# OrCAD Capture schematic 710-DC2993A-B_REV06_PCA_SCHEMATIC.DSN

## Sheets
1 PAGE1: size Custom
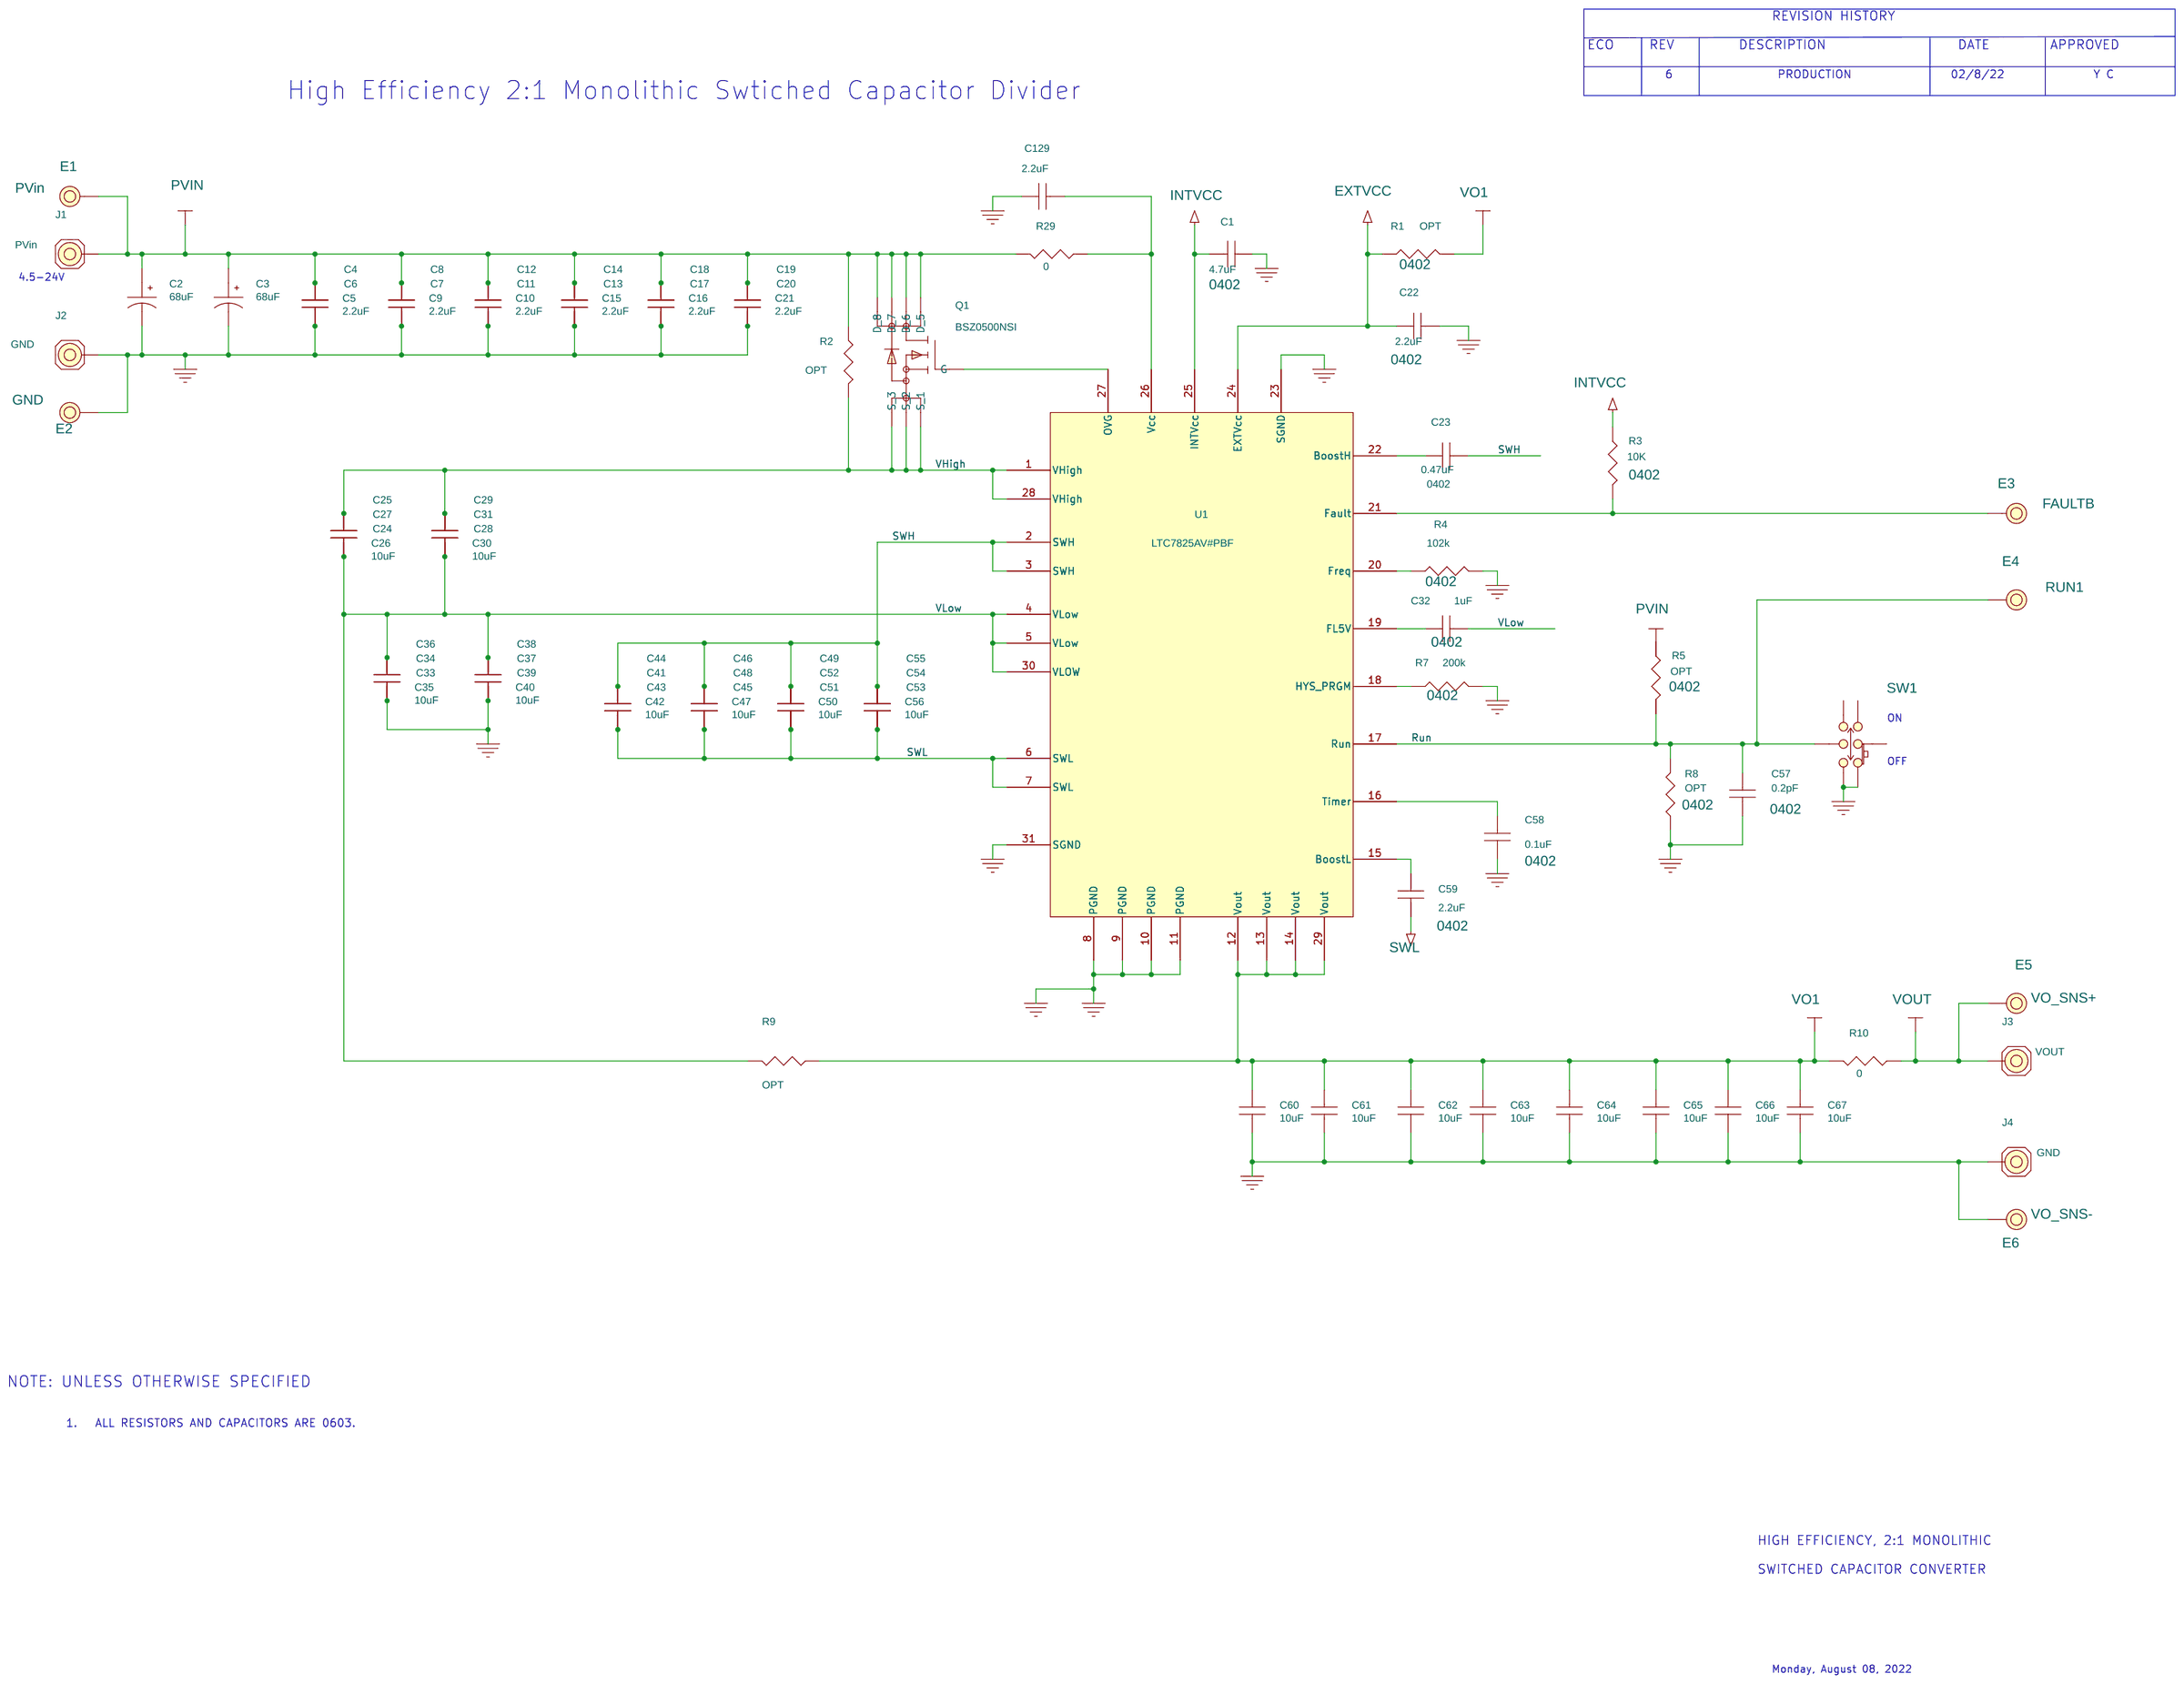
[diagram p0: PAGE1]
2 PAGE2: size Custom
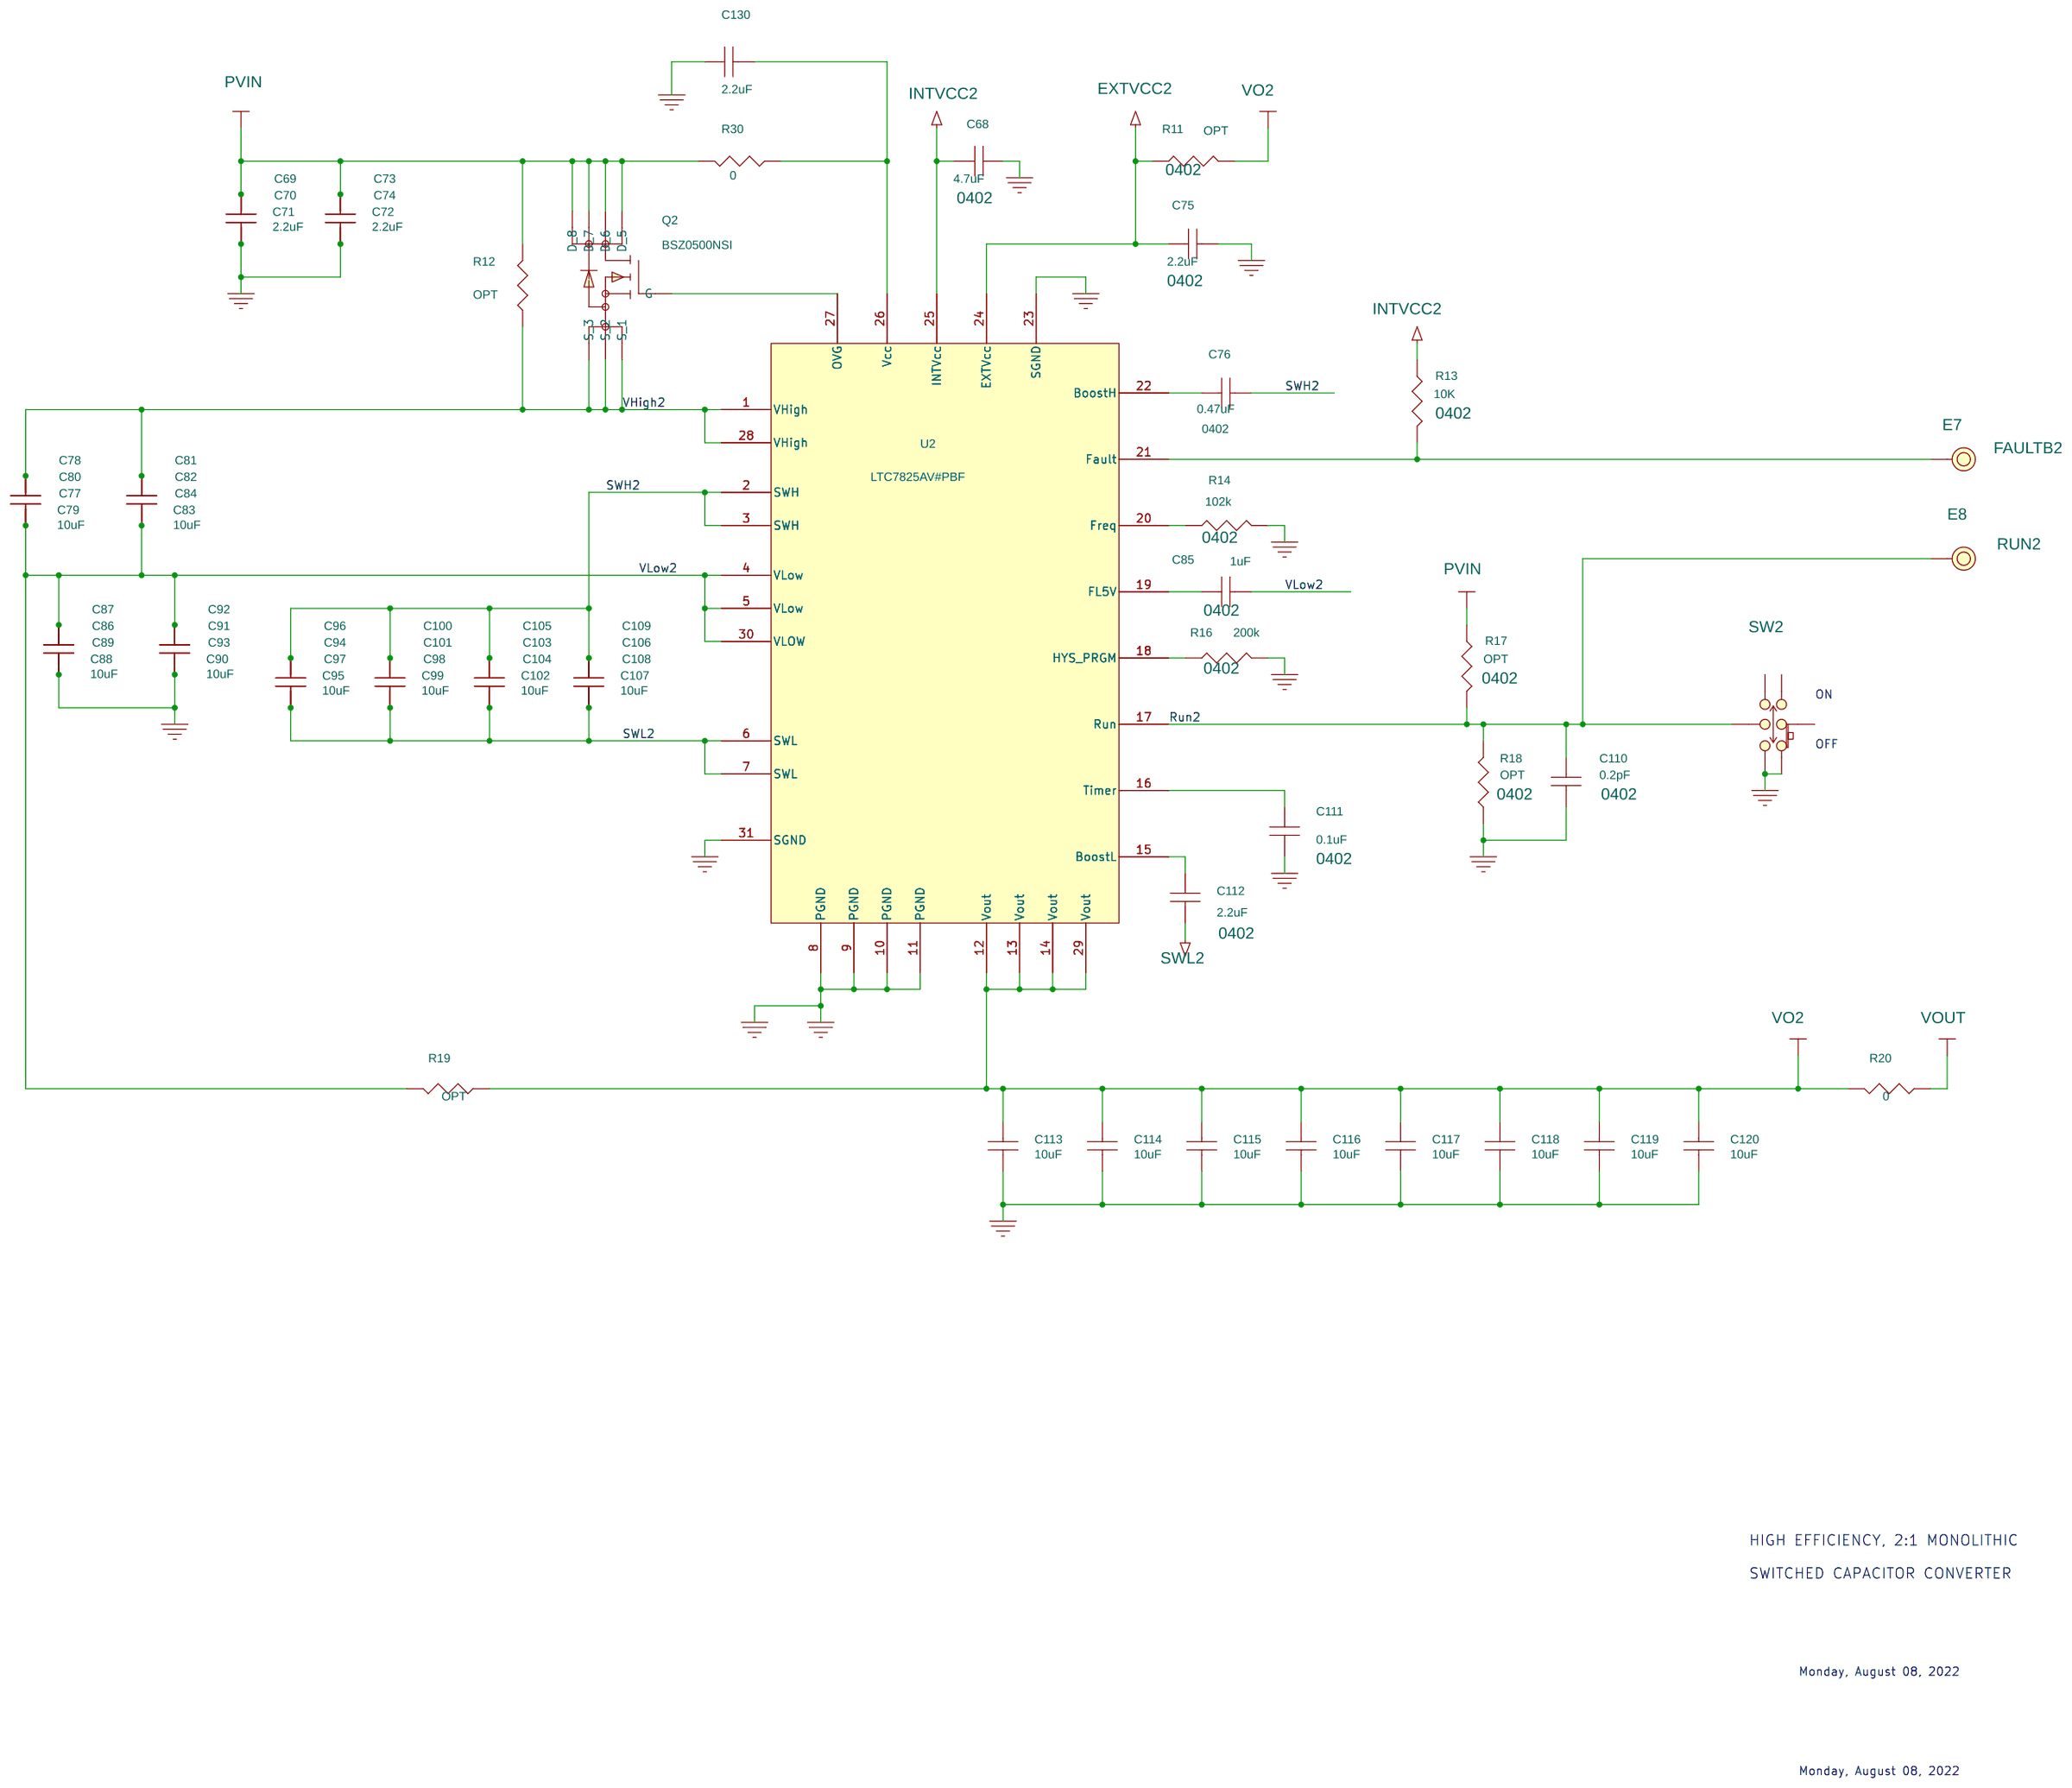
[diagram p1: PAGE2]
3 PAGE3: size Custom
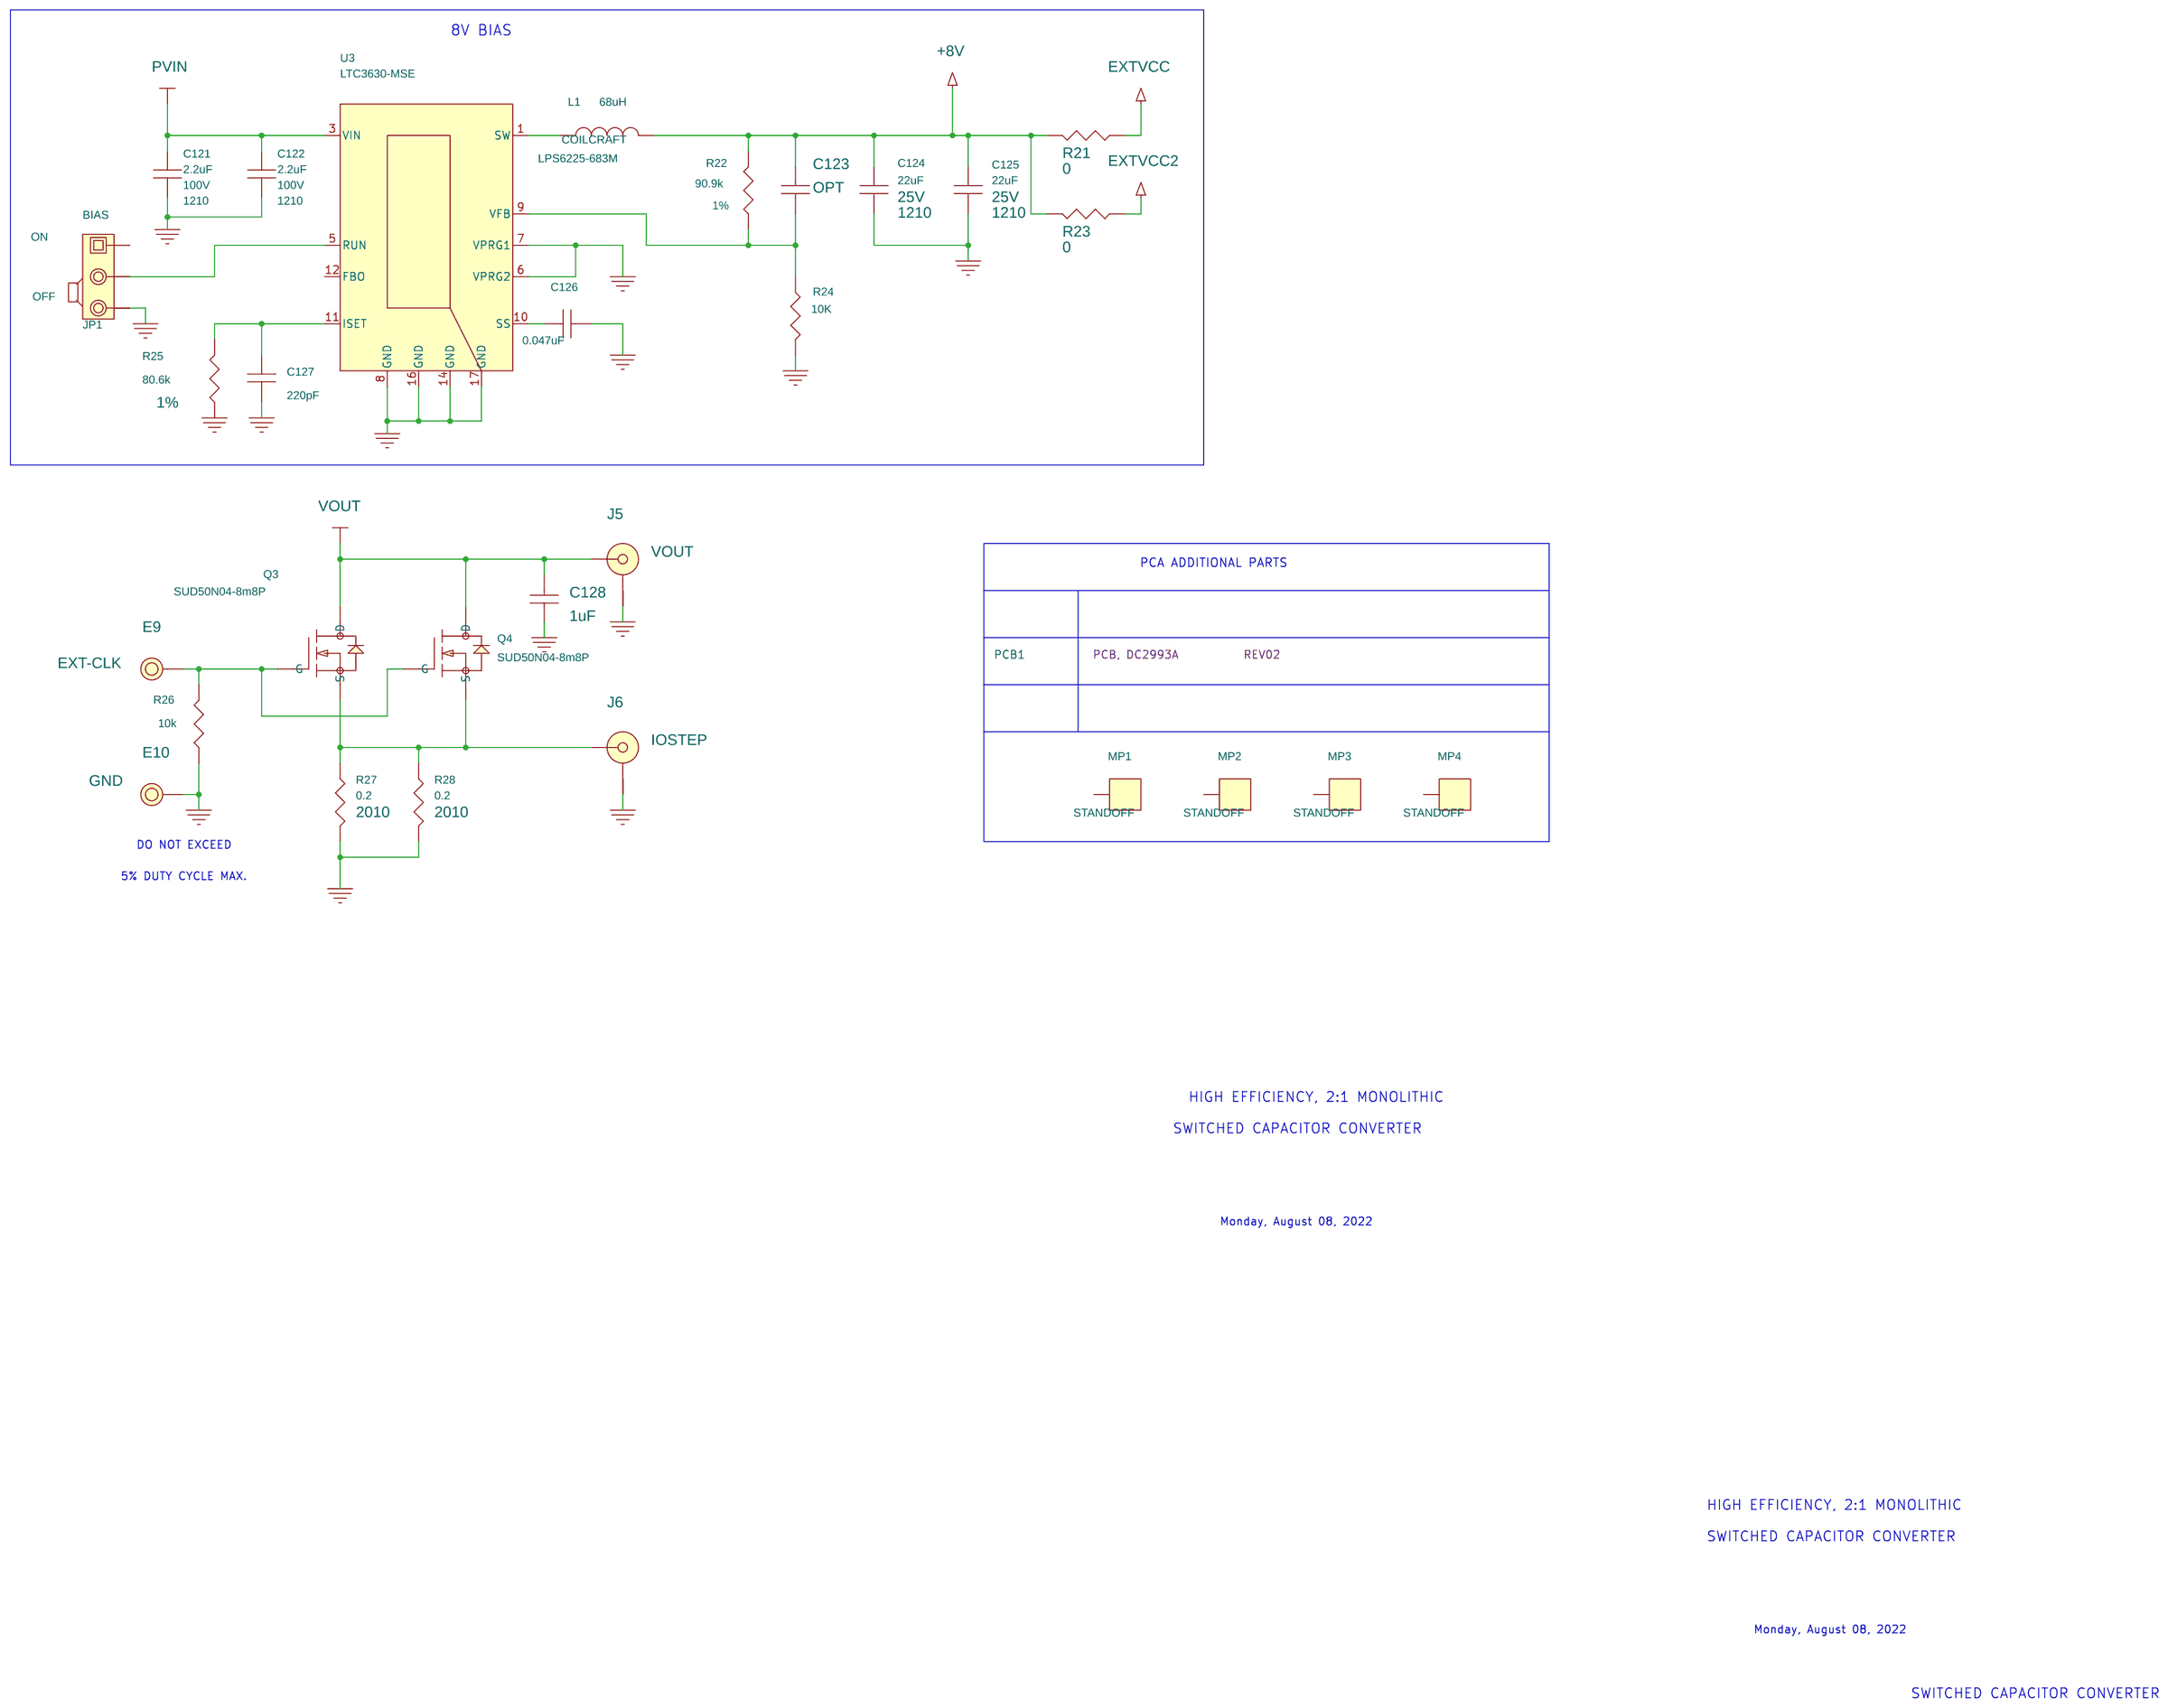
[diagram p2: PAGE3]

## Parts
sheet PAGE1
C1  4.7uF  [CC0402N]
C2  68uF  [NICHICON_GYA_8x10]
C3  68uF  [NICHICON_GYA_8x10]
C4  2.2uF  [CC0603N]
C5  2.2uF  [CC0603N]
C6  2.2uF  [CC0603N]
C7  2.2uF  [CC0603N]
C8  2.2uF  [CC0603N]
C9  2.2uF  [CC0603N]
C10  2.2uF  [CC0603N]
C11  2.2uF  [CC0603N]
C12  2.2uF  [CC0603N]
C13  2.2uF  [CC0603N]
C14  2.2uF  [CC0603N]
C15  2.2uF  [CC0603N]
C16  2.2uF  [CC0603N]
C17  2.2uF  [CC0603N]
C18  2.2uF  [CC0603N]
C19  2.2uF  [CC0603N]
C20  2.2uF  [CC0603N]
C21  2.2uF  [CC0603N]
C22  2.2uF  [CC0402N]
C23  0.47uF  [CC0402N]
C24  10uF  [CC0603N]
C25  10uF  [CC0603N]
C26  10uF  [CC0603N]
C27  10uF  [CC0603N]
C28  10uF  [CC0603N]
C29  10uF  [CC0603N]
C30  10uF  [CC0603N]
C31  10uF  [CC0603N]
C32  1uF  [CC0402N]
C33  10uF  [CC0603N]
C34  10uF  [CC0603N]
C35  10uF  [CC0603N]
C36  10uF  [CC0603N]
C37  10uF  [CC0603N]
C38  10uF  [CC0603N]
C39  10uF  [CC0603N]
C40  10uF  [CC0603N]
C41  10uF  [CC0603N]
C42  10uF  [CC0603N]
C43  10uF  [CC0603N]
C44  10uF  [CC0603N]
C45  10uF  [CC0603N]
C46  10uF  [CC0603N]
C47  10uF  [CC0603N]
C48  10uF  [CC0603N]
C49  10uF  [CC0603N]
C50  10uF  [CC0603N]
C51  10uF  [CC0603N]
C52  10uF  [CC0603N]
C53  10uF  [CC0603N]
C54  10uF  [CC0603N]
C55  10uF  [CC0603N]
C56  10uF  [CC0603N]
C57  0.2pF  [CC0402N]
C58  0.1uF  [CC0402N]
C59  2.2uF  [CC0402N]
C60  10uF  [CC0603N]
C61  10uF  [CC0603N]
C62  10uF  [CC0603N]
C63  10uF  [CC0603N]
C64  10uF  [CC0603N]
C65  10uF  [CC0603N]
C66  10uF  [CC0603N]
C67  10uF  [CC0603N]
C129  2.2uF  [CC0603N]
E1  TEST POINT  [MILLMAX2501]
E2  TEST POINT  [MILLMAX2501]
E3  TEST POINT  [MILLMAX2501]
E4  TEST POINT  [MILLMAX2501]
E5  TEST POINT  [MILLMAX2501]
E6  TEST POINT  [MILLMAX2501]
J1  STUD,#10-32  [PENN-KFH-032]
J2  STUD,#10-32  [PENN-KFH-032]
J3  STUD,#10-32  [PENN-KFH-032]
J4  STUD,#10-32  [PENN-KFH-032]
Q1  BSZ0500NSI  [INFINEON-PG-TSDSON-8-FL]
R1  OPT  [CR0402N]
R2  OPT  [CR0603N]
R3  10K  [CR0402N]
R4  102k  [CR0402N]
R5  OPT  [CR0402N]
R7  200k  [CR0402N]
R8  OPT  [CR0402N]
R9  OPT  [CR0603N]
R10  0  [CR0603N]
R29  0  [CR0603N]
SW1  DPDT  [C&K-JS202011CQN]
U1  LTC7825AV#PBF  [LTC-LQFN-28-7007]
sheet PAGE2
C68  4.7uF  [CC0402N]
C69  2.2uF  [CC0603N]
C70  2.2uF  [CC0603N]
C71  2.2uF  [CC0603N]
C72  2.2uF  [CC0603N]
C73  2.2uF  [CC0603N]
C74  2.2uF  [CC0603N]
C75  2.2uF  [CC0402N]
C76  0.47uF  [CC0402N]
C77  10uF  [CC0603N]
C78  10uF  [CC0603N]
C79  10uF  [CC0603N]
C80  10uF  [CC0603N]
C81  10uF  [CC0603N]
C82  10uF  [CC0603N]
C83  10uF  [CC0603N]
C84  10uF  [CC0603N]
C85  1uF  [CC0402N]
C86  10uF  [CC0603N]
C87  10uF  [CC0603N]
C88  10uF  [CC0603N]
C89  10uF  [CC0603N]
C90  10uF  [CC0603N]
C91  10uF  [CC0603N]
C92  10uF  [CC0603N]
C93  10uF  [CC0603N]
C94  10uF  [CC0603N]
C95  10uF  [CC0603N]
C96  10uF  [CC0603N]
C97  10uF  [CC0603N]
C98  10uF  [CC0603N]
C99  10uF  [CC0603N]
C100  10uF  [CC0603N]
C101  10uF  [CC0603N]
C102  10uF  [CC0603N]
C103  10uF  [CC0603N]
C104  10uF  [CC0603N]
C105  10uF  [CC0603N]
C106  10uF  [CC0603N]
C107  10uF  [CC0603N]
C108  10uF  [CC0603N]
C109  10uF  [CC0603N]
C110  0.2pF  [CC0402N]
C111  0.1uF  [CC0402N]
C112  2.2uF  [CC0402N]
C113  10uF  [CC0603N]
C114  10uF  [CC0603N]
C115  10uF  [CC0603N]
C116  10uF  [CC0603N]
C117  10uF  [CC0603N]
C118  10uF  [CC0603N]
C119  10uF  [CC0603N]
C120  10uF  [CC0603N]
C130  2.2uF  [CC0603N]
E7  TEST POINT  [MILLMAX2501]
E8  TEST POINT  [MILLMAX2501]
Q2  BSZ0500NSI  [INFINEON-PG-TSDSON-8-FL]
R11  OPT  [CR0402N]
R12  OPT  [CR0603N]
R13  10K  [CR0402N]
R14  102k  [CR0402N]
R16  200k  [CR0402N]
R17  OPT  [CR0402N]
R18  OPT  [CR0402N]
R19  OPT  [CR0603N]
R20  0  [CR0603N]
R30  0  [CR0603N]
SW2  DPDT  [C&K-JS202011CQN]
U2  LTC7825AV#PBF  [LTC-LQFN-28-7007]
sheet PAGE3
C121  2.2uF  [CC1210N]
C122  2.2uF  [CC1210N]
C123  OPT  [CC0603N]
C124  22uF  [CC1210N]
C125  22uF  [CC1210N]
C126  0.047uF  [CC0603N]
C127  220pF  [CC0603N]
C128  1uF  [CC0603N]
E9  TEST POINT  [MILLMAX2501]
E10  TEST POINT  [MILLMAX2501]
J5  RF,BNC  [CONNEX-112404]
J6  RF,BNC  [CONNEX-112404]
JP1  HDR  [HD1X3-079]
L1  68uH  [COILCRAFT-LPS6225]
LB1  LABEL  [895-0154_REV01]
LB4  LABEL  [895-0154_REV01]
LB5  LABEL  [EVAL-LTC4296-AZ]
MP1  STANDOFF  [KEYSTONE_8829-8834]
MP2  STANDOFF  [KEYSTONE_8829-8834]
MP3  STANDOFF  [KEYSTONE_8829-8834]
MP4  STANDOFF  [KEYSTONE_8829-8834]
PCB1  PCB, DC2993A
Q3  SUD50N04-8m8P  [TO-252-3N]
Q4  SUD50N04-8m8P  [TO-252-3N]
R21  0  [CR0603N]
R22  90.9k  [CR0603N]
R23  0  [CR0603N]
R24  10K  [CR0603N]
R25  80.6k  [CR0603N]
R26  10k  [CR0603N]
R27  0.2  [CR2010N]
R28  0.2  [CR2010N]
STNCL1  TOOL, STENCIL, 700-DC2993A
U3  LTC3630-MSE  [LTC-MSE-16-1871]
XJP1  SHUNT

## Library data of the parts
C1 C68 = CAP: CAP.,4.7uF,X5R,10V,10%,0402,NO SUBS. ALLOWED; CLASS: DISCRETE; Dielectric Type: X5R; FPLIST: CC0402N,CC0402L,CC0402M; Inventory Qty: 14000; Manufacturer: TDK; Manufacturer PN: C1005X5R1A475K050BC; PART_NUMBER: 150-2599; Package Size: 0402; Rated Voltage: 10V; Tolerance: 10%
C2 C3 = CAP_P_ALT: CAP.,68uF,ALUM POLY,50V,20%,SMD,8.3x8.3mm; CLASS: DISCRETE; Dielectric Type: ALUM POLY; Inventory Qty: 0; Manufacturer: Nichicon; Manufacturer PN: GYA1H680MCQ1GS; PART_NUMBER: 150-1214; Package Size: SMD,8.3x8.3mm; Package Type: Surface Mount; Rated Voltage: 50V; Tolerance: 20%
C4-C21 C69-C74 C129 C130 = CAP: CAP.,2.2uF,X5R,50V,10%,0603; CLASS: DISCRETE; Dielectric Type: X5R; FPLIST: CC0603N,CC0603L,CC0603M; Inventory Qty: 20200; Manufacturer: TAIYO YUDEN; Manufacturer PN: UMK107BBJ225KA-T; PART_NUMBER: 150-0229; Package Size: 0603; Package Type: Surface Mount, MLCC; Rated Voltage: 50V; Temperature Coefficient: X5R; Tolerance: 10%
C22 C59 C75 C112 = CAP: CAP.,2.2uF,X5R,25V,10%,0402; CLASS: DISCRETE; Dielectric Type: X5R; FPLIST: CC0402N,CC0402L,CC0402M; Inventory Qty: 19426; Manufacturer: MURATA; Manufacturer PN: GRM155R61E225KE11D; PART_NUMBER: 150-0271; Package Size: 0402; Rated Voltage: 25V; Tolerance: 10%
C23 C76 = CAP: CAP.,0.47uF,X5R,50V,10%,0402; CLASS: DISCRETE; Dielectric Type: X5R; FPLIST: CC0402N,CC0402L,CC0402M; Inventory Qty: 0; Manufacturer: MURATA; Manufacturer PN: GRM155R61H474KE11D; PART_NUMBER: 150-2644; Package Size: 0402; Rated Voltage: 50V; Tolerance: 10%
C24-C31 C33-C56 C60-C67 C77-C84 C86-C109 C113-C120 = CAP: CAP.,10uF,X5R,25V,20%,0603,NO SUBS. ALLOWED; CLASS: DISCRETE; Dielectric Type: X5R; FPLIST: CC0603N,CC0603L,CC0603M; Inventory Qty: 16160; Manufacturer: MURATA; Manufacturer PN: GRM188R61E106MA73D; PART_NUMBER: 150-2347; Package Size: 0603; Rated Voltage: 25V; Tolerance: 20%
C32 C85 = CAP: CAP.,1uF,X5R,25V,10%,0402; CLASS: DISCRETE; Dielectric Type: X5R; FPLIST: CC0402N,CC0402L,CC0402M; Inventory Qty: 20000; Manufacturer: MURATA; Manufacturer PN: GRM155R61E105KA12D; PART_NUMBER: 150-2562; Package Size: 0402; Rated Voltage: 25V; Tolerance: 10%
C57 C110 = CAP: CAP.,0.2pF,C0G,50V,+/-0.1pF,0402; CLASS: DISCRETE; Dielectric Type: C0G; FPLIST: CC0402N,CC0402L,CC0402M; Inventory Qty: 0; Manufacturer: MURATA; Manufacturer PN: GJM1555C1HR20BB01D; PART_NUMBER: 150-0532; Package Size: 0402; Rated Voltage: 50V; Tolerance: +/-0.1pF
C58 C111 = CAP: CAP.,0.1uF,X7R,25V,10%,0402,NO SUBS ALLOWED; CLASS: DISCRETE; Dielectric Type: X7R; FPLIST: CC0402N,CC0402L,CC0402M; Inventory Qty: 275; Manufacturer: MURATA; Manufacturer PN: GRM155R71E104KE14; PART_NUMBER: 150-0441; Package Size: 0402; Rated Voltage: 25V; Temperature Coefficient: X7R; Tolerance: 10%
E1 = TESTPOINT_.219_MILL-MAX_2501: TEST POINT,TURRET,0.094" MTG. HOLE,PCB 0.062" THK; 1st Part Field: PVin; CLASS: IO; Inventory Qty: 494204; Manufacturer: MILL-MAX; Manufacturer PN: 2501-2-00-80-00-00-07-0; PART_NUMBER: 260-0003; Part Number: MILL-MAX 2501-2-00-80-00-00-07-0
E2 E10 = TESTPOINT_.219_MILL-MAX_2501: TEST POINT,TURRET,0.094" MTG. HOLE,PCB 0.062" THK; 1st Part Field: GND; CLASS: IO; Inventory Qty: 494204; Manufacturer: MILL-MAX; Manufacturer PN: 2501-2-00-80-00-00-07-0; PART_NUMBER: 260-0003; Part Number: MILL-MAX 2501-2-00-80-00-00-07-0
E3 = TESTPOINT_.219_MILL-MAX_2501: TEST POINT,TURRET,0.094" MTG. HOLE,PCB 0.062" THK; 1st Part Field: FAULTB; CLASS: IO; Inventory Qty: 494204; Manufacturer: MILL-MAX; Manufacturer PN: 2501-2-00-80-00-00-07-0; PART_NUMBER: 260-0003; Part Number: MILL-MAX 2501-2-00-80-00-00-07-0
E4 = TESTPOINT_.219_MILL-MAX_2501: TEST POINT,TURRET,0.094" MTG. HOLE,PCB 0.062" THK; 1st Part Field: RUN1; CLASS: IO; Inventory Qty: 494204; Manufacturer: MILL-MAX; Manufacturer PN: 2501-2-00-80-00-00-07-0; PART_NUMBER: 260-0003; Part Number: MILL-MAX 2501-2-00-80-00-00-07-0
E5 = TESTPOINT_.219_MILL-MAX_2501: TEST POINT,TURRET,0.094" MTG. HOLE,PCB 0.062" THK; 1st Part Field: VO_SNS+; CLASS: IO; Inventory Qty: 494204; Manufacturer: MILL-MAX; Manufacturer PN: 2501-2-00-80-00-00-07-0; PART_NUMBER: 260-0003; Part Number: MILL-MAX 2501-2-00-80-00-00-07-0
E6 = TESTPOINT_.219_MILL-MAX_2501: TEST POINT,TURRET,0.094" MTG. HOLE,PCB 0.062" THK; 1st Part Field: VO_SNS-; CLASS: IO; Inventory Qty: 494204; Manufacturer: MILL-MAX; Manufacturer PN: 2501-2-00-80-00-00-07-0; PART_NUMBER: 260-0003; Part Number: MILL-MAX 2501-2-00-80-00-00-07-0
J1 = PEM-KFH: EVAL BOARD STUD HARDWARE SET, #10-32; 9th Part Field: PVin; CLASS: DISCRETE; Comments: CONSISTS OF QTY(1) STUD, 769-0012; QTY(1) RING LUG, 769-0013;QTY(2) HEX NUT,BRASS,761-0013; QTY(1) WASHER,#10 LOCK, 762-0021; Manufacturer: ANALOG DEVICES; Manufacturer PN: 720-0010; PART_NUMBER: 720-0010
J2 J4 = PEM-KFH: EVAL BOARD STUD HARDWARE SET, #10-32; 9th Part Field: GND; CLASS: DISCRETE; Comments: CONSISTS OF QTY(1) STUD, 769-0012; QTY(1) RING LUG, 769-0013;QTY(2) HEX NUT,BRASS,761-0013; QTY(1) WASHER,#10 LOCK, 762-0021; Manufacturer: ANALOG DEVICES; Manufacturer PN: 720-0010; PART_NUMBER: 720-0010
J3 = PEM-KFH: EVAL BOARD STUD HARDWARE SET, #10-32; 9th Part Field: VOUT; CLASS: DISCRETE; Comments: CONSISTS OF QTY(1) STUD, 769-0012; QTY(1) RING LUG, 769-0013;QTY(2) HEX NUT,BRASS,761-0013; QTY(1) WASHER,#10 LOCK, 762-0021; Manufacturer: ANALOG DEVICES; Manufacturer PN: 720-0010; PART_NUMBER: 720-0010
Q1 Q2 = 8P_N-CH_TYPE1A: XSTR.,MOSFET,N-CH,30V,40A,PG-TSDSON-8 FL; CLASS: DISCRETE; Inventory Qty: 0; Manufacturer: INFINEON; PART_NUMBER: 240-0470; Package Type: PG-TSDSON-8 FL; Rated Voltage: 30V
R1 R5 R8 R11 R17 R18 = RES: RES., OPTION, 0402; CLASS: DISCRETE; FPLIST: CR0402N,CR0402L,CR0402M; PART_NUMBER: 100-0357; Package Size: 0402
R2 R9 R12 R19 = RES: RES., OPTION, 0603; CLASS: DISCRETE; FPLIST: CR0603N,CR0603L,CR0603M; PART_NUMBER: 100-2374; Package Size: 0603
R3 R13 = RES: RES.,10K OHMS,0.1%,1/16W,0402; CLASS: DISCRETE; FPLIST: CR0402N,CR0402L,CR0402M; Inventory Qty: 19766; Manufacturer: YAGEO; Manufacturer PN: RT0402BRD0710KL; PART_NUMBER: 100-0575; Package Size: 0402; Rated Power: 1/16W; Temperature Coefficient: +/-25PPM; Tolerance: 0.1%
R4 R14 = RES: RES.,102k OHMS,1%,1/16W,0402,AEC-Q200; CLASS: DISCRETE; Inventory Qty: 33884; Manufacturer: STACKPOLE ELECTRONICS, INC.; Manufacturer PN: RMCF0402FT102K; PART_NUMBER: 100-2539; Package Size: 0402; Rated Power: 1/16W; Temperature Coefficient: 100ppm/C; Tolerance: 1%
R7 R16 = RES: RES.,200k OHMS,1%,1/16W,0402; CLASS: DISCRETE; Inventory Qty: 77068; Manufacturer: NIC; Manufacturer PN: NRC04F2003TRF; PART_NUMBER: 100-0329; Package Size: 0402; Rated Power: 1/16W; Temperature Coefficient: 100ppm/C; Tolerance: 1%
R10 R20 R29 R30 = RES: RES.,0 OHMS,1/10W,0603,Metal Strip  AEC-Q200; CLASS: DISCRETE; Manufacturer: VISHAY; Manufacturer PN: WSL060300000ZEA9; PART_NUMBER: 100-1494; Package Size: 0603; Rated Power: 1/10W; Temperature Coefficient: 3900PPM/*C; Tolerance: Z for jumper
SW1 SW2 = SW-DPDT-JS202011CQN_ALT1: SWITCH,SLIDE,DPDT,0.3A,6VDC,PTH; CLASS: DISCRETE; Inventory Qty: 22357; Manufacturer: C&K; Manufacturer PN: JS202011CQN; PART_NUMBER: 430-0039; Part Number: C&K JS202011CQN
U1 U2 = LTC7825-LQFN_0: IC,High Efficiency,2:1 Step-Down Ratio,Switched Capacitor Converter; CLASS: IC; Inventory Qty: 0; Manufacturer: ANALOG DEVICES, INC.; Manufacturer PN: LTC7825EUFD#PBF; PART_NUMBER: LTC7825EUFD#PBF; Package Size: 3mmX3mmX0.75mm; Package Type: 16-pin MSOP
E7 = TESTPOINT_.219_MILL-MAX_2501: TEST POINT,TURRET,0.094" MTG. HOLE,PCB 0.062" THK; 1st Part Field: FAULTB2; CLASS: IO; Inventory Qty: 494204; Manufacturer: MILL-MAX; Manufacturer PN: 2501-2-00-80-00-00-07-0; PART_NUMBER: 260-0003; Part Number: MILL-MAX 2501-2-00-80-00-00-07-0
E8 = TESTPOINT_.219_MILL-MAX_2501: TEST POINT,TURRET,0.094" MTG. HOLE,PCB 0.062" THK; 1st Part Field: RUN2; CLASS: IO; Inventory Qty: 494204; Manufacturer: MILL-MAX; Manufacturer PN: 2501-2-00-80-00-00-07-0; PART_NUMBER: 260-0003; Part Number: MILL-MAX 2501-2-00-80-00-00-07-0
C121 C122 = CAP: CAP.,2.2uF,X7R,100V,10%,1210; CLASS: DISCRETE; Dielectric Type: X7R; FPLIST: CC1210N,CC1210L,CC1210M; Inventory Qty: 5692; Manufacturer: TDK; Manufacturer PN: C3225X7R2A225K230AB; PART_NUMBER: 150-3012; Package Size: 1210; Part Number: VJ1210Y225MXBCW1BC; Rated Voltage: 100V; Tolerance: 10%
C123 = CAP: CAP., OPTION, 0603; CLASS: DISCRETE; FPLIST: CC0603N,CC0603L,CC0603M; PART_NUMBER: 150-3038; Package Size: 0603; Package Type: SMD; Part Number: OPTION; UserField01: OPTION
C124 C125 = CAP: CAP.,22uF,X5R,25V,10%,1210; CLASS: DISCRETE; Dielectric Type: X5R; FPLIST: CC1210N,CC1210L,CC1210M; Inventory Qty: 17144; Manufacturer: KEMET; Manufacturer PN: C1210C226K3PACTU; PART_NUMBER: 150-3033; Package Size: 1210; Package Type: SMD; Rated Voltage: 25V; Tolerance: 10%
C126 = CAP: CAP.,0.047uF,X7R,50V,10%,0603; CLASS: DISCRETE; Dielectric Type: X7R; FPLIST: CC0603N,CC0603L,CC0603M; Inventory Qty: 11990; Manufacturer: AVX; Manufacturer PN: 06035C473KAT2A; PART_NUMBER: 150-0097; Package Size: 0603; Rated Voltage: 50V; Tolerance: 10%
C127 = CAP: CAP.,220pF,X7R,50V,10%,0603; CLASS: DISCRETE; Dielectric Type: X7R; FPLIST: CC0603N,CC0603L,CC0603M; Inventory Qty: 35278; Manufacturer: AVX; Manufacturer PN: 06035C221KAT2A; PART_NUMBER: 150-0062; Package Size: 0603; Rated Voltage: 50V; Tolerance: 10%
C128 = CAP: CAP.,1uF,X7R,25V,10%,0603; CLASS: DISCRETE; Dielectric Type: X7R; FPLIST: CC0603N,CC0603L,CC0603M; Inventory Qty: 35994; Manufacturer: MURATA; Manufacturer PN: GRM188R71E105KA12D; PART_NUMBER: 150-3372; Package Size: 0603; Package Type: SMD; Part Number: C1608X7R1E105K080AB; Rated Voltage: 25V; Tolerance: 10%
E9 = TESTPOINT_.219_MILL-MAX_2501: TEST POINT,TURRET,0.094" MTG. HOLE,PCB 0.062" THK; 1st Part Field: EXT-CLK; CLASS: IO; Inventory Qty: 494204; Manufacturer: MILL-MAX; Manufacturer PN: 2501-2-00-80-00-00-07-0; PART_NUMBER: 260-0003; Part Number: MILL-MAX 2501-2-00-80-00-00-07-0
J5 = BNC_50_OHM_112404_B: CONN.,RF,BNC,RCPT JACK,5-PIN,STR,THT,50 OHMS; 1st Part Field: VOUT; CLASS: IO; Inventory Qty: 84371; Manufacturer: AMPHENOL RF; Manufacturer PN: 112404; PART_NUMBER: 250-0427; Part Number: 112404
J6 = BNC_50_OHM_112404_B: CONN.,RF,BNC,RCPT JACK,5-PIN,STR,THT,50 OHMS; 1st Part Field: IOSTEP; CLASS: IO; Inventory Qty: 84371; Manufacturer: AMPHENOL RF; Manufacturer PN: 112404; PART_NUMBER: 250-0427; Part Number: 112404
JP1 = 1X3_A: CONN.,HDR,MALE,1x3,2mm,VERT,STR,THT,NO SUBS. ALLOWED; 11th Part Field: OFF; 12th Part Field: BIAS; 9th Part Field: ON; CLASS: IO; Inventory Qty: 21620; Manufacturer: Wurth Elektronik; Manufacturer PN: 62000311121; PART_NUMBER: 250-0639; Part Number: WURTH 620 003 111 21
L1 = IND: IND.,68uH,PWR, SHIELDED,20%,0.74A,0.42 OHM,2424, LPS6225; 5TH PART FIELD: COILCRAFT; 7TH PART FIELD: LPS6225-683M; CLASS: DISCRETE; Inventory Qty: 793; Manufacturer: Coilcraft; Manufacturer PN: LPS6225-683MRB; PART_NUMBER: 200-0477; Package Size: 2424, LPS6225; Tolerance: 20%
LB1 = BLANK_LABEL: LABEL SPEC, DEMO BOARD SERIAL NUMBER; Inventory Qty: 0; Manufacturer: BRADY; Manufacturer PN: THT-96-717-10; PART_NUMBER: 895-0154
LB4 = BLANK_LABEL: LABEL SPEC, DEMO BOARD SERIAL NUMBER; CLASS: DISCRETE; Inventory Qty: 0; Manufacturer: ANALOG DEVICES; Manufacturer PN: EVAL-LT4200-A1Z; PART_NUMBER: TMP-7416
LB5 = BLANK_LABEL: LABEL SPEC, DEMO BOARD SERIAL NUMBER; CLASS: DISCRETE; Inventory Qty: 0; Manufacturer: ANALOG DEVICES; Manufacturer PN: 600-EVAL-LTC4296-AZ; PART_NUMBER: TMP-7264
MP1-MP4 = MP-PINNED: STANDOFF,NYLON,SNAP-ON,0.625"; CLASS: DISCRETE; Inventory Qty: 145547; Manufacturer: KEYSTONE; Manufacturer PN: 8834; PART_NUMBER: 763-0013
PCB1 = BLANK_PCB_PART: BOM Notes: REV02; CLASS: DISCRETE; Manufacturer: LINEAR TECH.; Manufacturer PN: 600-DC2993A; PART_NUMBER: 600-DC2993A
Q3 Q4 = 3P_N-CH_TYPE2A: XSTR.,MOSFET,N-CH,40V,14A,TO-252 (DPAK); CLASS: DISCRETE; FPLIST: TO-252-3N,TO-252-3L,TO-252-3M; Inventory Qty: 21562; Manufacturer: VISHAY; Manufacturer PN: SUD50N04-8M8P-4GE3; PART_NUMBER: 240-0021; Package Type: TO-252 (DPAK); Rated Voltage: 40V
R21 R23 = RES: RES.,0 OHM,1/10W,0603,AEC-Q200; CLASS: DISCRETE; FPLIST: CR0603N,CR0603L,CR0603M; Inventory Qty: 603973; Manufacturer: VISHAY; Manufacturer PN: CRCW06030000Z0EA; PART_NUMBER: 100-0009; Package Size: 0603; Part Number: CRCW06030000Z0EA; Rated Power: 1/10W
R22 = RES: RES.,90.9k OHMS,1%,1/10W,0603,AEC-Q200; CLASS: DISCRETE; FPLIST: CR0603N,CR0603L,CR0603M; Inventory Qty: 76804; Manufacturer: VISHAY; Manufacturer PN: CRCW060390K9FKEA; PART_NUMBER: 100-2379; Package Size: 0603; Part Number: CRCW0603154KFKEA; Rated Power: 1/10W; Temperature Coefficient: 100ppm/C; Tolerance: 1%
R24 = RES: RES.,10K OHMS,1%,1/10W,0603,AEC-Q200; CLASS: DISCRETE; FPLIST: CR0603N,CR0603L,CR0603M; Inventory Qty: 25324; Manufacturer: PANASONIC; Manufacturer PN: ERJ3EKF1002V; PART_NUMBER: 100-0602; Package Size: 0603; Rated Power: 1/10W; Temperature Coefficient: 100PPM; Tolerance: 1%
R25 = RES: RES.,80.6k OHMS,1%,1/10W,0603; CLASS: DISCRETE; FPLIST: CR0603N,CR0603L,CR0603M; Inventory Qty: 42208; Manufacturer: VISHAY; Manufacturer PN: CRCW060380K6FKEA; PART_NUMBER: 100-2503; Package Size: 0603; Rated Power: 1/10W; Temperature Coefficient: 100ppm/C; Tolerance: 1%
R26 = RES: RES.,10k OHMS,1%,1/10W,0603; CLASS: DISCRETE; FPLIST: CR0603N,CR0603L,CR0603M; Inventory Qty: 74903; Manufacturer: VISHAY; Manufacturer PN: CRCW060310K0FKEC; PART_NUMBER: 100-2532; Package Size: 0603; Part Number: NRC06F1002TRF; Rated Power: 1/10W; Temperature Coefficient: 100ppm/C; Tolerance: 1%
R27 R28 = RES: RES.,0.2 OHM,1%,1/2W,2010,SENSE, AEC-Q200; CLASS: DISCRETE; FPLIST: CR2010N,CR2010L,CR2010M; Inventory Qty: 7630; Manufacturer: VISHAY; Manufacturer PN: WSL2010R2000FEA; PART_NUMBER: 100-1095; Package Size: 2010; Part Number: WSL2010R0100FEA18; Rated Power: 1/2W; Temperature Coefficient: +/-75ppm; Tolerance: 1%
STNCL1 = BLANK_STENCIL_PART: BOM Notes: REV01; CLASS: DISCRETE; Inventory Qty: 0; Manufacturer: ANALOG DEVICES, INC.; Manufacturer PN: 830-DC2993A; PART_NUMBER: 830-DC2993A
U3 = LTC3630-MSE: IC,Synchr. Step-Down Converter,MSOP-16 (MSE),76V, 500mA; CLASS: IC; Inventory Qty: 395; Manufacturer: LINEAR TECH.; Manufacturer PN: LTC3630AEMSE#PBF; PART_NUMBER: LTC3630AEMSE#PBF; Package Type: MSOP-16 (MSE)
XJP1 = SHUNT_2MM: CONN.,SHUNT,FEMALE,2 POS,2mm; CLASS: IO; Inventory Qty: 65650; Manufacturer: Wurth Elektronik; Manufacturer PN: 60800213421; PART_NUMBER: 250-0485; Part Number: WURTH ELEKTRONIK 60800213421

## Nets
+8V: C123.1 C124.1 C125.1 L1.2 R21.1 R22.2 R23.1
GND: C1.1 C2.2 C3.2 C4.2 C5.2 C6.2 C7.2 C8.2 C9.2 C10.2 C11.2 C12.2 C13.2 C14.2 C15.2 C16.2 C17.2 C18.2 C19.2 C20.2 C21.2 C22.2 C33.2 C34.2 C35.2 C36.2 C37.2 C38.2 C39.2 C40.2 C57.2 C58.2 C60.2 C61.2 C62.2 C63.2 C64.2 C65.2 C66.2 C67.2 C68.1 C69.2 C70.2 C71.2 C72.2 C73.2 C74.2 C75.2 C86.2 C87.2 C88.2 C89.2 C90.2 C91.2 C92.2 C93.2 C110.2 C111.2 C113.2 C114.2 C115.2 C116.2 C117.2 C118.2 C119.2 C120.2 C121.2 C122.2 C124.2 C125.2 C126.2 C127.2 C128.1 C129.1 C130.1 E2.1 E6.1 E10.1 J2.1 J4.1 J5.2 J5.3 J5.4 J5.5 J6.2 J6.3 J6.4 J6.5 JP1.3 R4.2 R7.2 R8.1 R14.2 R16.2 R18.1 R24.2 R25.2 R26.2 R27.2 R28.2 SW1.3 SW1.6 SW2.3 SW2.6 U1.8(PGND) U1.9(PGND) U1.10(PGND) U1.11(PGND) U1.23(SGND) U1.31(SGND) U2.8(PGND) U2.9(PGND) U2.10(PGND) U2.11(PGND) U2.23(SGND) U2.31(SGND) U3.6(VPRG2) U3.7(VPRG1) U3.8(GND) U3.14(GND) U3.16(GND) U3.17(GND)
PVin: C2.1 C3.1 C4.1 C5.1 C6.1 C7.1 C8.1 C9.1 C10.1 C11.1 C12.1 C13.1 C14.1 C15.1 C16.1 C17.1 C18.1 C19.1 C20.1 C21.1 C69.1 C70.1 C71.1 C72.1 C73.1 C74.1 C121.1 C122.1 E1.1 J1.1 Q1.5(D) Q1.6(D) Q1.7(D) Q1.8(D) Q2.5(D) Q2.6(D) Q2.7(D) Q2.8(D) R2.2 R5.1 R12.1 R17.1 R29.1 R30.1 U3.3(VIN)
EXTVCC: C22.1 R1.1 R21.2 U1.24(EXTVcc)
EXTVCC2: C75.1 R11.1 R23.2 U2.24(EXTVcc)
INTVCC: C1.2 R3.1 U1.25(INTVcc)
INTVCC2: C68.2 R13.1 U2.25(INTVcc)
Run: C57.1 E4.1 R5.2 R8.2 SW1.5 U1.17(Run)
Run2: C110.1 E8.1 R17.2 R18.2 SW2.5 U2.17(Run)
SWH: C23.2 C41.1 C42.1 C43.1 C44.1 C45.1 C46.1 C47.1 C48.1 C49.1 C50.1 C51.1 C52.1 C53.1 C54.1 C55.1 C56.1 U1.2(SWH) U1.3(SWH)
SWH2: C76.2 C94.1 C95.1 C96.1 C97.1 C98.1 C99.1 C100.1 C101.1 C102.1 C103.1 C104.1 C105.1 C106.1 C107.1 C108.1 C109.1 U2.2(SWH) U2.3(SWH)
SWL: C41.2 C42.2 C43.2 C44.2 C45.2 C46.2 C47.2 C48.2 C49.2 C50.2 C51.2 C52.2 C53.2 C54.2 C55.2 C56.2 C59.2 U1.6(SWL) U1.7(SWL)
SWL2: C94.2 C95.2 C96.2 C97.2 C98.2 C99.2 C100.2 C101.2 C102.2 C103.2 C104.2 C105.2 C106.2 C107.2 C108.2 C109.2 C112.2 U2.6(SWL) U2.7(SWL)
VHigh: C24.1 C25.1 C26.1 C27.1 C28.1 C29.1 C30.1 C31.1 Q1.1(S) Q1.2(S) Q1.3(S) R2.1 U1.1(VHigh) U1.28(VHigh)
VHigh2: C77.1 C78.1 C79.1 C80.1 C81.1 C82.1 C83.1 C84.1 Q2.1(S) Q2.2(S) Q2.3(S) R12.2 U2.1(VHigh) U2.28(VHigh)
VLow: C24.2 C25.2 C26.2 C27.2 C28.2 C29.2 C30.2 C31.2 C32.2 C33.1 C34.1 C35.1 C36.1 C37.1 C38.1 C39.1 C40.1 R9.1 U1.4(VLow) U1.5(VLow) U1.30(VLOW)
VLow2: C77.2 C78.2 C79.2 C80.2 C81.2 C82.2 C83.2 C84.2 C85.2 C86.1 C87.1 C88.1 C89.1 C90.1 C91.1 C92.1 C93.1 R19.1 U2.4(VLow) U2.5(VLow) U2.30(VLOW)
Vo1: C60.1 C61.1 C62.1 C63.1 C64.1 C65.1 C66.1 C67.1 R1.2 R9.2 R10.1 U1.12(Vout) U1.13(Vout) U1.14(Vout) U1.29(Vout)
Vo2: C113.1 C114.1 C115.1 C116.1 C117.1 C118.1 C119.1 C120.1 R11.2 R19.2 R20.1 U2.12(Vout) U2.13(Vout) U2.14(Vout) U2.29(Vout)
VOUT: C128.2 E5.1 J3.1 J5.1 Q3.2(D) Q4.2(D) R10.2 R20.2
N26722873: E3.1 R3.2 U1.21(Fault)
N26722999: C58.1 U1.16(Timer)
N27480431: Q1.4(G) U1.27(OVG)
N27480436: C129.2 R29.2 U1.26(Vcc)
N27484546: R7.1 U1.18(HYS_PRGM)
N27485596: R4.1 U1.20(Freq)
N27487414: C23.1 U1.22(BoostH)
N27487417: C32.1 U1.19(FL5V)
N27487420: C59.1 U1.15(BoostL)
N27569809: E7.1 R13.2 U2.21(Fault)
N27569811: C111.1 U2.16(Timer)
N27569899: Q2.4(G) U2.27(OVG)
N27569900: C130.2 R30.2 U2.26(Vcc)
N27569920: R16.1 U2.18(HYS_PRGM)
N27569923: R14.1 U2.20(Freq)
N27569931: C76.1 U2.22(BoostH)
N27569932: C85.1 U2.19(FL5V)
N27569933: C112.1 U2.15(BoostL)
N27578014: L1.1 U3.1(SW)
N27578134: C123.2 R22.1 R24.1 U3.9(VFB)
N27578159: JP1.2 U3.5(RUN)
N27578213: C127.1 R25.1 U3.11(ISET)
N27578221: C126.1 U3.10(SS)
N27578715: E9.1 Q3.1(G) Q4.1(G) R26.1
N27578737: J6.1 Q3.3(S) Q4.3(S) R27.1 R28.1

Not connected (* = marked no-connect by the designer): JP1 1; MP1 1; MP2 1; MP3 1; MP4 1; SW1 1 2 4; SW2 1 2 4; U3 12(FBO)

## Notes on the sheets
sheet 1
- REVISION HISTORY
- ECO
- REV
- DESCRIPTION
- DATE
- APPROVED
- High Efficiency 2:1 Monolithic Swtiched Capacitor Divider
- 6
- PRODUCTION
- 02/8/22
- Y C
- 4.5-24V
- ON
- OFF
- NOTE: UNLESS OTHERWISE SPECIFIED
- 1.   ALL RESISTORS AND CAPACITORS ARE 0603.
- HIGH EFFICIENCY, 2:1 MONOLITHIC
- SWITCHED CAPACITOR CONVERTER
- Monday, August 08, 2022
sheet 2
- ON
- OFF
- HIGH EFFICIENCY, 2:1 MONOLITHIC
- SWITCHED CAPACITOR CONVERTER
- Monday, August 08, 2022
- Monday, August 08, 2022
sheet 3
- 8V BIAS
- PCA ADDITIONAL PARTS
- DO NOT EXCEED
- 5% DUTY CYCLE MAX.
- HIGH EFFICIENCY, 2:1 MONOLITHIC
- SWITCHED CAPACITOR CONVERTER
- Monday, August 08, 2022
- HIGH EFFICIENCY, 2:1 MONOLITHIC
- SWITCHED CAPACITOR CONVERTER
- Monday, August 08, 2022
- SWITCHED CAPACITOR CONVERTER
